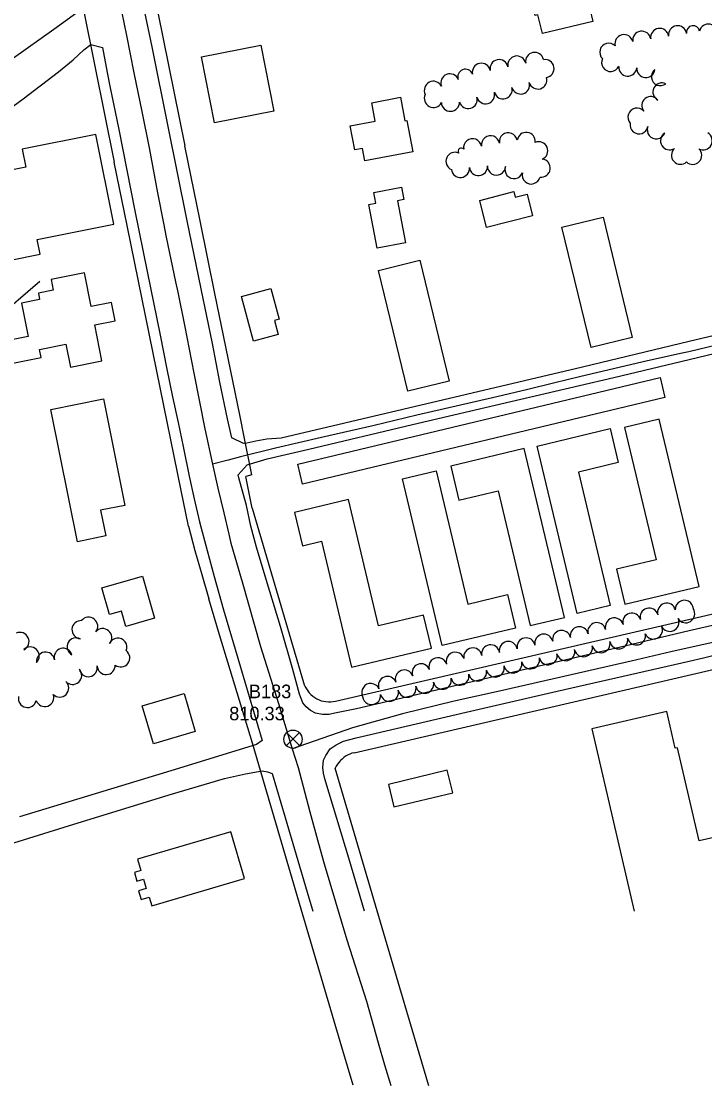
# Model space of a CAD drawing. Extents: x -25029 to 2274964, y -81170 to 687028.
# Drawn here: x -18399 to -17644, y -68941 to -67765 of the extents above; entities that cross this region are included whole.
import ezdxf

# ---------------------------------------------------------------- set-up
doc = ezdxf.new("R2010")
doc.units = 0
for name, color, linetype in [('81911BEA - RW_X_Fee_RW', 7, 'Continuous'), ('BLDG', 7, 'Continuous'), ('GE_X_CL_2000', 7, 'Continuous'), ('ROAD', 7, 'Continuous'), ('TI_VER', 7, 'Continuous'), ('TREES', 7, 'Continuous'), ('WALL', 7, 'Continuous')]:
    doc.layers.add(name, color=color, linetype=linetype)

msp = doc.modelspace()

# ---------------------------------------------------------------- linework, layer by layer
at = {"layer": '81911BEA - RW_X_Fee_RW'}
for p, q in [((-18201.4, -67985.5), (-18218.3, -67903)), ((-18144, -68266.4), (-18150.8, -68268)), ((-18143.8, -68303), (-18150.8, -68268)), ((-18214.2, -68322.8), (-18222.2, -68283.5)), ((-18143.8, -68303), (-18087.1, -68495.5)), ((-18051.6, -68516.3), (-17611.5, -68414.4)), ((-18031.2, -68573.2), (-17594.5, -68472.1))]:
    msp.add_line(p, q, dxfattribs=at)
for points in [[(-18265.5, -67668.3), (-18253.9, -67726), (-18218.3, -67903)], [(-18344, -67684.1), (-18342.8, -67690), (-18317.6, -67814.9), (-18296.3, -67920.9)], [(-18222.2, -68283.5), (-18249.1, -68151.8), (-18282, -67990.7), (-18296.3, -67920.9)], [(-18144, -68266.4), (-18152.7, -68224.1), (-18157.2, -68201.7), (-18170.3, -68137.5), (-18185, -68066), (-18201.4, -67985.6)], [(-18214.2, -68322.8), (-18207, -68349.7), (-18199.5, -68376.5), (-18191.7, -68403.2)], [(-18143.5, -68562.7), (-18179.7, -68443), (-18191.7, -68403.2)], [(-18087.1, -68495.5), (-18086.2, -68498.1), (-18085.2, -68500.5), (-18083.9, -68502.8), (-18082.4, -68505), (-18080.7, -68507.1), (-18078.8, -68509), (-18076.8, -68510.7), (-18074.6, -68512.3), (-18072.3, -68513.6), (-18069.9, -68514.8), (-18067.4, -68515.7), (-18064.8, -68516.4), (-18062.2, -68516.8), (-18059.5, -68517.1), (-18056.8, -68517), (-18054.2, -68516.8), (-18051.6, -68516.3)], [(-18032.3, -68940.3), (-18044.7, -68898.4), (-18065.2, -68828.4), (-18093.2, -68733.4), (-18129.3, -68610.6), (-18143.5, -68562.7)], [(-18031.2, -68573.2), (-18033.6, -68573.8), (-18036, -68574.7), (-18038.3, -68575.8), (-18040.5, -68577.1), (-18042.6, -68578.5), (-18044.5, -68580.2), (-18046.3, -68581.9), (-18048, -68583.9), (-18049.5, -68585.9), (-18050.8, -68588.1), (-18051.9, -68590.4)], [(-17948.7, -68941), (-17980.5, -68833), (-18051.9, -68590.4)]]:
    msp.add_lwpolyline(points, dxfattribs=at)
at = {"layer": 'BLDG'}
for points in [[(-17800, -67717.9), (-17797.6, -67728), (-17777.3, -67723.2), (-17767.2, -67765.6), (-17823, -67778.9), (-17828, -67758), (-17830.9, -67758.7), (-17838.4, -67727)], [(-18185.5, -67877.5), (-18199.9, -67804.6), (-18134.2, -67791.6), (-18119.8, -67864.5)], [(-18021.9, -67905.6), (-18030.5, -67907.2), (-18035.5, -67880.8), (-18007.8, -67875.6), (-18011.6, -67855.2), (-17979.9, -67849.2), (-17975, -67875.1), (-17972.7, -67874.7), (-17966.2, -67909.4), (-18019.3, -67919.5)], [(-18398, -67906.6), (-18394, -67926.3), (-18429.2, -67933.4), (-18428.9, -67934.9), (-18453, -67939.7), (-18443.4, -67987.2), (-18422.1, -67982.9), (-18412.7, -68029.5), (-18378, -68022.5), (-18381.3, -68006.3), (-18296.7, -67989.3), (-18316.6, -67890.2)], [(-18007.1, -67966.1), (-18009.4, -67954.2), (-17978.8, -67948.4), (-17976.2, -67962.1), (-17983, -67963.4), (-17974.3, -68009.8), (-18005.8, -68015.8), (-18014.9, -67967.6)], [(-17892.3, -67963.1), (-17854.6, -67953.4), (-17853, -67959.7), (-17840, -67956.4), (-17834, -67980), (-17884.7, -67992.9)], [(-17756.1, -67981.5), (-17723.8, -68114.4), (-17769.3, -68125.5), (-17801.6, -67992.6)], [(-17958.4, -68029.2), (-17926, -68162.6), (-17971.9, -68173.8), (-18004.3, -68040.4)], [(-18365.9, -68050.4), (-18363.5, -68062.3), (-18380, -68065.6), (-18378.6, -68072.5), (-18398.8, -68076.6), (-18391.4, -68113.3), (-18419, -68118.9), (-18413.9, -68144.1), (-18377.1, -68136.7), (-18378.9, -68127.7), (-18349.6, -68121.8), (-18344.4, -68147.4), (-18309.8, -68140.4), (-18317.8, -68100.6), (-18295.3, -68096.1), (-18299.3, -68075.9), (-18321.6, -68080.4), (-18329.1, -68043)], [(-18123.1, -68060.6), (-18114.1, -68094.3), (-18119.1, -68095.6), (-18115, -68111.3), (-18142.4, -68118.6), (-18155.7, -68069.3)], [(-17687.7, -68180.8), (-18088, -68276.4), (-18093.3, -68254.3), (-17693, -68158.7)], [(-18308, -68182.2), (-18284.3, -68300), (-18311.3, -68305.4), (-18305.6, -68333.8), (-18336.8, -68340.1), (-18366.2, -68193.9)], [(-17732.3, -68214), (-17697.4, -68360.1), (-17741.3, -68370.6), (-17732.1, -68409.2), (-17649.8, -68389.5), (-17693.9, -68204.8)], [(-17748.2, -68215.2), (-17739.3, -68252.7), (-17783.3, -68263.2), (-17748.1, -68410.7), (-17784.5, -68419.4), (-17828.7, -68234.4)], [(-17924.3, -68256.6), (-17915.4, -68294.2), (-17872.1, -68283.9), (-17836.5, -68432.8), (-17798.8, -68423.8), (-17843.3, -68237.3)], [(-17940.5, -68261.8), (-17905.3, -68409.1), (-17861.6, -68398.6), (-17852.8, -68435.6), (-17933.8, -68454.9), (-17977.8, -68270.7)], [(-18096.9, -68307.7), (-18088.1, -68344.6), (-18067.1, -68339.6), (-18033.9, -68478.6), (-17945.7, -68457.6), (-17954.3, -68421.3), (-18004.1, -68433.1), (-18037.5, -68293.5)], [(-18251.6, -68424.7), (-18283.4, -68433.7), (-18288.1, -68417), (-18301.4, -68420.7), (-18309.8, -68391), (-18264.8, -68378.2)], [(-18219, -68507.9), (-18206.7, -68549.7), (-18252.9, -68563.3), (-18265.2, -68521.5)], [(-17987.2, -68633.1), (-17922.2, -68617.4), (-17928.2, -68592.6), (-17993.2, -68608.3)], [(-18167.4, -68660.7), (-18270.3, -68690.9), (-18266.7, -68703.2), (-18273.9, -68705.4), (-18271.1, -68715), (-18263.9, -68712.9), (-18260.9, -68723.3), (-18269.2, -68725.7), (-18266.4, -68735.2), (-18257.6, -68732.6), (-18254.8, -68742.3), (-18152.2, -68712.2)]]:
    msp.add_lwpolyline(points, close=True, dxfattribs=at)
msp.add_lwpolyline([(-17551.5, -68748.4), (-17556.3, -68727.6), (-17608.3, -68739.6), (-17625.7, -68665.1), (-17649.9, -68670.7), (-17673.8, -68567.7), (-17676.2, -68568.3), (-17685.7, -68527.5), (-17768.6, -68546.8), (-17721.8, -68748.4)], dxfattribs=at)
at = {"layer": 'GE_X_CL_2000'}
for points in [[(-18297.5, -67706.5), (-18291.3, -67739.5), (-18287.8, -67756.1), (-18282.5, -67780.9), (-18274.6, -67822.1), (-18265.6, -67864.8), (-18257.5, -67905), (-18248.2, -67954.9), (-18241.8, -67988.3), (-18238.8, -68003.7), (-18228.4, -68053.1), (-18226, -68064.4), (-18218.5, -68101), (-18208.4, -68153.8), (-18196, -68215.6), (-18187.6, -68254.5)], [(-17609.4, -68117.9), (-17661.1, -68130.3), (-17668.7, -68132), (-17706.9, -68140.4), (-17780.7, -68157.5), (-17810.7, -68165), (-17839.1, -68172.1), (-17873.4, -68179.9), (-17900.8, -68186.2), (-17961.7, -68200.5), (-18010.5, -68212), (-18067.2, -68225.1), (-18118, -68236.9), (-18156.6, -68246.2), (-18170.3, -68249.9), (-18187.6, -68254.5)], [(-18187.6, -68254.5), (-18181.8, -68281.1), (-18175.2, -68308.3), (-18169.4, -68331.9), (-18167.2, -68341.9), (-18154.9, -68384.3), (-18134.6, -68455.7), (-18114.8, -68518.7), (-18099.4, -68568.8)], [(-17015.5, -68335.9), (-17065.8, -68338.3), (-17123.5, -68342.4), (-17165.6, -68347.3), (-17191.9, -68351.1), (-17227.3, -68357.3), (-17260.7, -68364.3), (-17369.7, -68390.5), (-17506.5, -68422.1), (-17612.7, -68446.4), (-17619.9, -68448), (-17681.3, -68461.6), (-17725, -68472), (-17791.4, -68487.2), (-17870.3, -68505.3), (-17920.7, -68516.3), (-17977.8, -68530.3), (-18032.8, -68545.7), (-18099.4, -68568.8)], [(-18099.4, -68568.8), (-18093.1, -68589.5), (-18080, -68638.6), (-18070.5, -68673.4), (-18064.3, -68695.9), (-18039.3, -68779.8), (-18017.3, -68847.6), (-18004.4, -68893.7), (-17997.6, -68918.1), (-17990.5, -68940.7)]]:
    msp.add_lwpolyline(points, dxfattribs=at)
at = {"layer": 'ROAD'}
for points in [[(-18399.3, -67346.7), (-18365.5, -67517.3), (-18322.4, -67729.7), (-18320.2, -67743.3), (-18362.8, -67774.4), (-18407.5, -67806)], [(-17660.9, -68118.9), (-17778.9, -68147.2), (-17907.1, -68177.5), (-18111.6, -68225.7), (-18127.5, -68227), (-18139.8, -68229), (-18149.8, -68231.3), (-18153.2, -68231.8), (-18166.4, -68225.2), (-18171.1, -68204.5), (-18179.4, -68163.7), (-18187.7, -68121.3), (-18200.3, -68060.8), (-18216.1, -67983.8), (-18236.5, -67881.3), (-18254.4, -67793.4), (-18262.7, -67753.4)], [(-18449.7, -67889.4), (-18396.8, -67850.9), (-18357.9, -67821), (-18341.5, -67807.7), (-18329.7, -67796.7), (-18322, -67791), (-18309.3, -67794.2), (-18304, -67821.8), (-18301, -67837), (-18291, -67884.9), (-18273.4, -67974.6), (-18259.7, -68041.7), (-18245.3, -68112.1), (-18238, -68149.5), (-18231.8, -68179.9), (-18225.7, -68208.4), (-18219.9, -68235.1), (-18213.5, -68267.6), (-18208, -68292.8), (-18201.8, -68318.2), (-18193.4, -68350), (-18185.6, -68378.5), (-18175.3, -68415.4), (-18156.8, -68478.7), (-18132.8, -68559.6), (-18138.9, -68564.3), (-18233.7, -68593.2), (-18401, -68644)], [(-17660.9, -68138.7), (-17622.7, -68129.8), (-17471.7, -68094.9), (-17305.9, -68055.9), (-17194.2, -68029), (-17058.1, -67997.6), (-16993.4, -67983.2), (-16904.5, -67962.1), (-16908.3, -67943.7), (-17042.7, -67974.2), (-17236.5, -68018.8), (-17484.1, -68077.7), (-17583, -68100.6), (-17660.9, -68118.9)], [(-17661, -68438.6), (-17731.8, -68455.4), (-18028.5, -68524.7), (-18050.6, -68529.3), (-18059, -68530.9), (-18066.1, -68530.9), (-18073.7, -68529.4), (-18079.4, -68526.5), (-18084.2, -68522.4), (-18087.6, -68518.1), (-18091.3, -68508.4), (-18098.9, -68481.1), (-18112.5, -68433.6), (-18128.3, -68382), (-18138.8, -68346), (-18145.3, -68323), (-18150.2, -68300), (-18158.5, -68269.6), (-18159.1, -68266.4), (-18149.3, -68255.1), (-18127.2, -68248.7), (-18081.3, -68237.8), (-17966.6, -68210.6), (-17858.1, -68185.4), (-17744.1, -68158.6), (-17660.9, -68138.7)], [(-17661, -68471.9), (-17645.2, -68468.4), (-17607.9, -68459.3), (-17585.7, -68453.2), (-17553, -68442.6), (-17513.2, -68433.1), (-17439.1, -68416.3), (-17410.4, -68409.3), (-17381.7, -68402.7), (-17358, -68397.7), (-17320.3, -68388.7), (-17293.1, -68382.7), (-17271.6, -68378), (-17253.4, -68374.7), (-17233.2, -68370.8), (-17212.1, -68367.3), (-17187.3, -68363.3), (-17157.3, -68359), (-17131.5, -68356.1), (-17105.1, -68353.4), (-17080.2, -68351.2), (-17059.1, -68349.9), (-17041.3, -68348.9), (-17021.3, -68348.3)], [(-17366.1, -68374.1), (-17469.4, -68398.5), (-17555.1, -68418.1), (-17569.6, -68420.9), (-17592, -68423.9), (-17610.5, -68427), (-17627, -68430.7), (-17661, -68438.6)], [(-18515.4, -68427.8), (-18508.6, -68436.6), (-18502.8, -68448), (-18498.5, -68457.2), (-18490.1, -68481.3), (-18486.2, -68495.4), (-18453.2, -68618.3), (-18435.9, -68681.4), (-18351.5, -68655.6), (-18235.4, -68619.8), (-18174.4, -68601.6), (-18151.3, -68596.4), (-18132.9, -68593.3), (-18126.9, -68594.4), (-18121.6, -68596.2), (-18107.3, -68644.9), (-18083, -68727.1), (-18076.8, -68748.4)], [(-18019.5, -68748.4), (-18035.8, -68693.5), (-18063.4, -68602.2), (-18065, -68595.8), (-18065.7, -68589.6), (-18065, -68581.5), (-18062.3, -68576.1), (-18057.4, -68568.9), (-18051, -68564.4), (-18042.7, -68560.5), (-18028.8, -68556.9), (-17907.4, -68528.5), (-17806.9, -68505.2), (-17661, -68471.9)]]:
    msp.add_lwpolyline(points, dxfattribs=at)
at = {"layer": 'TI_VER'}
for p, q in [((-18106, -68551), (-18091.6, -68565.4)), ((-18098.8, -68558.2), (-18106, -68565.4)), ((-18098.8, -68558.2), (-18091.6, -68551))]:
    msp.add_line(p, q, dxfattribs=at)
msp.add_circle((-18098.6, -68558.3), 10.1, dxfattribs=at)
at = {"layer": 'TREES'}
for centre, radius, start, end in [((-17673.7, -67780.1), 10, 8.7693, 188.7693), ((-17656.6, -67777.4), 7.3, 8.7693, 188.7693), ((-17639.6, -67778.3), 10, 348.5206, 168.5206), ((-17732.9, -67790), 10, 13.3272, 193.3272), ((-17713.3, -67786.2), 10, 8.7693, 188.7693), ((-17693.5, -67783.1), 10, 8.7693, 188.7693), ((-17749.7, -67799.4), 10, 45.0635, 225.0635), ((-17851.3, -67813.6), 10, 11.5045, 191.5045), ((-17831.7, -67809.6), 10, 11.5045, 191.5045), ((-17890.5, -67821.6), 10, 11.5045, 191.5045), ((-17870.9, -67817.6), 10, 11.5045, 191.5045), ((-17820.2, -67817.5), 10, 280.08, 100.08), ((-17747.7, -67810.7), 10, 154.7593, 334.7593), ((-17728.7, -67815.8), 10, 175.6396, 355.6396), ((-17708.8, -67817.5), 10, 174.3161, 354.3161), ((-17925.3, -67833.3), 10, 21.3134, 201.3134), ((-17908.2, -67826.6), 8.43, 21.3134, 201.3134), ((-17828, -67830.1), 10, 196.4075, 16.4075), ((-17692.7, -67826.4), 10, 127.7436, 307.7436), ((-17943.6, -67841.5), 10, 26.7596, 206.7596), ((-17866.5, -67841), 10, 195.5678, 15.5678), ((-17847.2, -67835.6), 10, 195.5678, 15.5678), ((-17691, -67843.3), 10, 63.9198, 243.9198), ((-17943.6, -67850.5), 10, 153.2229, 333.2229), ((-17905, -67851.7), 10, 195.5678, 15.5678), ((-17885.8, -67846.4), 10, 195.5678, 15.5678), ((-17703.3, -67858.4), 10, 37.9038, 217.9038), ((-17924.7, -67854.7), 10, 181.6061, 1.6061), ((-17718.6, -67871.2), 10, 41.3617, 221.3617), ((-17860.7, -67898.4), 10, 9.482, 189.482), ((-17840.9, -67897.9), 10, 353.2551, 173.2551), ((-17716.3, -67879.6), 10, 169.4852, 349.4852), ((-17697.2, -67885.1), 10, 158.3036, 338.3036), ((-17645.3, -67897.3), 10, 240.919, 60.919), ((-17900.2, -67905), 10, 9.482, 189.482), ((-17880.4, -67901.7), 10, 9.482, 189.482), ((-17827.1, -67908.3), 10, 293.1316, 113.1316), ((-17682.6, -67897.3), 10, 122.2732, 302.2732), ((-17919.6, -67919.9), 10, 66.2266, 246.2266), ((-17912.8, -67908.7), 3.44, 36.4811, 216.4811), ((-17670.5, -67913.2), 10, 131.9728, 311.9728), ((-17657, -67913.3), 10, 226.7494, 46.7494), ((-17824.4, -67927.4), 10, 262.6519, 82.6519), ((-17913.7, -67927.8), 10, 186.6687, 6.6687), ((-17893.8, -67925.8), 10, 185.1586, 5.1586), ((-17873.9, -67925.2), 10, 177.9777, 357.9777), ((-17854.5, -67929.1), 10, 159.2574, 339.2574), ((-17835.4, -67935), 10, 166.6027, 346.6027), ((-17666.2, -68414.8), 10, 2.6134, 182.6134), ((-17705.1, -68423.4), 10, 15.7783, 195.7783), ((-17685.8, -68418), 10, 15.7783, 195.7783), ((-17664.7, -68419.7), 10, 212.0449, 32.0449), ((-18332.9, -68437.3), 10, 86.2489, 266.2489), ((-18324.4, -68433.5), 10, 321.8844, 141.8844), ((-17743.6, -68434.3), 10, 15.7783, 195.7783), ((-17724.3, -68428.9), 10, 15.7783, 195.7783), ((-17682.2, -68429.2), 10, 204.8436, 24.8436), ((-18400.3, -68450.3), 10, 294.485, 114.485), ((-18308.9, -68446.1), 10, 319.6597, 139.6597), ((-17801.9, -68448.1), 10, 11.7389, 191.7389), ((-17782.3, -68444), 10, 11.7389, 191.7389), ((-17762.9, -68439.5), 10, 14.4144, 194.4144), ((-17700.4, -68437.6), 10, 204.8436, 24.8436), ((-18338.3, -68456.1), 10, 62.2565, 242.2565), ((-18292.1, -68456.6), 10, 336.7843, 156.7843), ((-17860.7, -68460.3), 10, 11.7389, 191.7389), ((-17841.1, -68456.3), 10, 11.7389, 191.7389), ((-17821.5, -68452.2), 10, 11.7389, 191.7389), ((-17758.3, -68452.7), 10, 192.9657, 12.9657), ((-17738.7, -68448.5), 10, 190.8246, 10.8246), ((-17719.2, -68444.2), 10, 194.1344, 14.1344), ((-18389, -68466.4), 10, 315.2627, 135.2627), ((-18372, -68472), 10, 8.2447, 188.2447), ((-18352.5, -68467.8), 10, 16.1883, 196.1883), ((-18289, -68468.4), 10, 232.5983, 52.5983), ((-17919.4, -68472.2), 10, 17.4814, 197.4814), ((-17900, -68467.4), 10, 10.1916, 190.1916), ((-17880.3, -68464), 10, 9.4428, 189.4428), ((-17816.7, -68466.1), 10, 192.9657, 12.9657), ((-17797.2, -68461.6), 10, 192.9657, 12.9657), ((-17777.7, -68457.2), 10, 192.9657, 12.9657), ((-18305.1, -68476.9), 10, 182.8801, 2.8801), ((-17957.2, -68484.7), 9.78, 20.9467, 200.9467), ((-17938.5, -68478.2), 10, 17.4814, 197.4814), ((-17855.7, -68475.1), 10, 192.9657, 12.9657), ((-17836.2, -68470.6), 10, 192.9657, 12.9657), ((-18342.1, -68487.8), 10, 222.1664, 42.1664), ((-18324.9, -68479.2), 10, 190.661, 10.661), ((-17975.6, -68491.8), 10, 20.9467, 200.9467), ((-17914.2, -68488.6), 10, 192.9657, 12.9657), ((-17894.7, -68484.1), 10, 192.9657, 12.9657), ((-17875.2, -68479.6), 10, 192.9657, 12.9657), ((-18356.5, -68501.7), 10, 225.5131, 45.5131), ((-18012.7, -68506.7), 10, 25.186, 205.186), ((-17994.3, -68498.9), 10, 20.9467, 200.9467), ((-17972.6, -68502), 10, 192.9657, 12.9657), ((-17953.2, -68497.5), 10, 192.9657, 12.9657), ((-17933.7, -68493.1), 10, 192.9657, 12.9657), ((-18392.1, -68513.3), 10, 167.1479, 347.1479), ((-18373, -68512.2), 10, 199.7948, 19.7948), ((-18011.8, -68509.9), 10, 186.4217, 6.4217), ((-17992.1, -68506.5), 10, 192.9657, 12.9657)]:
    msp.add_arc(centre, radius, start, end, dxfattribs=at)
at = {"layer": 'WALL'}
msp.add_lwpolyline([(-18493.5, -68122.1), (-18479.8, -68139.3), (-18378.5, -68052.3)], dxfattribs=at)

# ---------------------------------------------------------------- texts
at = {"layer": 'TI_VER'}
for s, p in [('B183', (-18147.4, -68513)), ('810.33', (-18169.1, -68537.4))]:
    msp.add_text(s, height=15, dxfattribs=at).set_placement(p)

doc.saveas('drawing.dxf')
